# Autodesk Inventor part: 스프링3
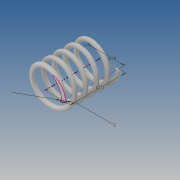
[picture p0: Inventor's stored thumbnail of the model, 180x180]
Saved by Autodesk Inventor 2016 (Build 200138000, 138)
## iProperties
Created: 2016-10
Part Number: 스프링3
Material: Generic
Document SubType Name: Modeling
Designer: Administrator
Density: 1 g/cm^3
Appearance: Default
Author: Administrator
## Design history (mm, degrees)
sketch "스케치1"
  geometry: L1 (0, 0)-(-9, 0); L2 (-9, 0)-(-9, -27); L3 (-9, -27)-(0, -27); L4 (0, -27)-(0, 0); C1 r 1 at (-9, 0)
  constraints: 8 end point, 2 parallel, 1 centre point, 1 coincident, 1 horizontal, 1 perpendicular
  dimensions: "d0" = 2 diameter of C1; "d1" = 27 distance of L1.end L2.end (derived); "d2" = 18 diameter of L2 L4
feature "코일1" pitch "d3" = 10; turns "d5" = 5; dims "d4" = 27 (= d1), "d6" = 0, angle "d7" = 90 deg, angle "d8" = 90 deg, "d9" = 0, "d10" = 0
sketch "스케치2"
  geometry: L1 (10, 0)-(8, 0) reference; 1 further point
  constraints: 1 horizontal alignment
  node "절단 모서리 투영1"
extrude "돌출1" cut sketch "스케치2" stored distance "d11" = 10; taper "d12" = 0 deg
node "작업 평면3"
sketch "스케치3"
  geometry: L1 (-1, 0)-(1, 0) reference; 1 further point
  constraints: 1 horizontal alignment
extrude "돌출2" cut sketch "스케치3" stored distance "d14" = 0; taper "d15" = 0 deg
node "솔리드1"
node "절단 모서리 투영2"
other parameters: "d13" = 90 deg
